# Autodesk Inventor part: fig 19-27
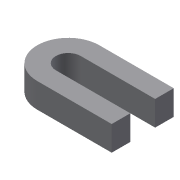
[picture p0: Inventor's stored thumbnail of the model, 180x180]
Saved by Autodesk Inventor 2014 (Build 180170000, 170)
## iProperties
Created: 2013-07
Part Number: fig 19-27
Material: Generic
Document SubType Name: Modeling
Designer: CADCIM
Density: 1 g/cm^3
Appearance: Default
Author: CADCIM
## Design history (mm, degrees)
sketch "Sketch1"
  geometry: L1 (0, 12.5)-(30, 12.5); L2 (0, -12.5)-(30, -12.5); L3 (30, -12.5)-(30, -5); L4 (30, -5)-(0, -5); L5 (30, 12.5)-(30, 5); L6 (30, 5)-(0, 5); A1 r 12.5 centre (0, 0) between (0, 12.5) and (0, -12.5); A2 r 5 centre (0, 0) between (0, 5) and (0, -5); 1 further point
  constraints: 12 end point, 4 point on circle, 3 perpendicular, 2 centre point, 2 coincident, 2 parallel, 2 tangent, 1 horizontal
  dimensions: "d3" = 7.5 distance of L2.end L3.end; "d4" = 7.5 distance of L1.end L5.end
extrude "Extrusion1" new body sketch "Sketch1" distance "d5" = 10; taper "d6" = 0 deg
body "Solid1"
